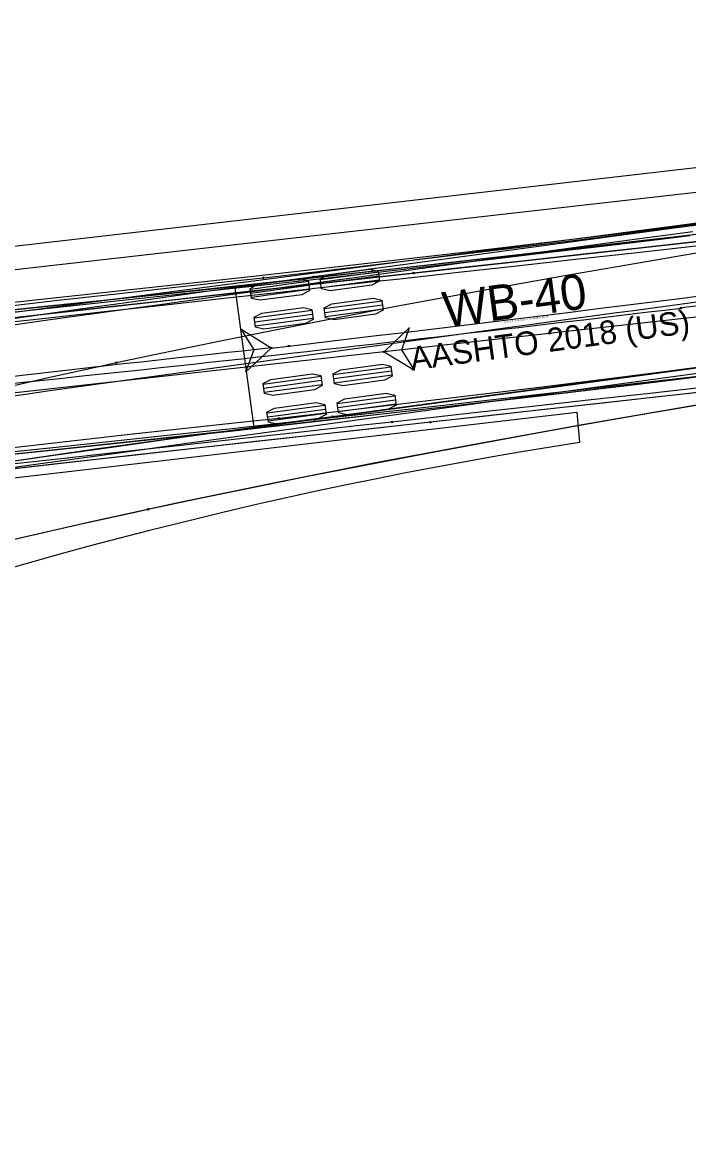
# Model space of a CAD drawing. Extents: x 1600240 to 1604759, y 285789 to 289704.
# Drawn here: x 1601719 to 1601756.7, y 286670.3 to 286733.3 of the extents above; entities that cross this region are included whole.
import ezdxf

# ---------------------------------------------------------------- set-up
doc = ezdxf.new("R2010")
doc.units = 0
for name, color, linetype in [('MT_P_CL_Double_Solid', 7, 'Continuous'), ('MT_P_Drums', 7, 'Continuous'), ('MT_X_CL_Double_Solid', 7, 'Continuous'), ('MT_X_Edge_Line', 7, 'Continuous'), ('PM_X_Edge_Line', 7, 'Continuous'), ('TR_Turning_Path2', 7, 'Continuous'), ('TR_Turning_Path3', 7, 'Continuous'), ('TR_Turning_Path4', 7, 'Continuous')]:
    doc.layers.add(name, color=color, linetype=linetype)

msp = doc.modelspace()

# ---------------------------------------------------------------- linework, layer by layer
at = {"layer": 'MT_P_CL_Double_Solid'}
for p, q in [((1601763.729, 286722.673), (1601731.025, 286718.262)), ((1601739.133, 286719.124), (1601735.862, 286718.683)), ((1601739.163, 286718.897), (1601735.893, 286718.456)), ((1601731.025, 286718.262), (1601732.095, 286710.333)), ((1601735.169, 286718.589), (1601731.898, 286718.148)), ((1601735.199, 286718.362), (1601731.929, 286717.921)), ((1601735.23, 286718.135), (1601731.959, 286717.694)), ((1601739.194, 286718.67), (1601735.924, 286718.229)), ((1601735.389, 286716.954), (1601732.119, 286716.513)), ((1601739.353, 286717.489), (1601736.083, 286717.048)), ((1601739.384, 286717.262), (1601736.113, 286716.82)), ((1601739.414, 286717.035), (1601736.144, 286716.593)), ((1601735.42, 286716.727), (1601732.149, 286716.286)), ((1601735.45, 286716.5), (1601732.18, 286716.059)), ((1601732.095, 286710.333), (1601764.798, 286714.745)), ((1601739.859, 286713.739), (1601736.589, 286713.298)), ((1601735.895, 286713.205), (1601732.624, 286712.764)), ((1601739.89, 286713.512), (1601736.619, 286713.071)), ((1601739.92, 286713.285), (1601736.65, 286712.844)), ((1601735.926, 286712.978), (1601732.655, 286712.536)), ((1601735.956, 286712.75), (1601732.686, 286712.309)), ((1601740.08, 286712.104), (1601736.809, 286711.663)), ((1601740.11, 286711.877), (1601736.84, 286711.436)), ((1601736.115, 286711.569), (1601732.845, 286711.128)), ((1601736.146, 286711.342), (1601732.876, 286710.901)), ((1601740.141, 286711.65), (1601736.87, 286711.209)), ((1601736.177, 286711.115), (1601732.906, 286710.674))]:
    msp.add_line(p, q, dxfattribs=at)
for points in [[(1601732.634, 286718.801), (1601734.278, 286718.988), (1601737.577, 286719.38), (1601740.876, 286719.776), (1601744.174, 286720.176), (1601747.472, 286720.58), (1601750.77, 286720.987), (1601754.067, 286721.398), (1601757.363, 286721.813), (1601760.659, 286722.232), (1601763.955, 286722.654), (1601767.25, 286723.081), (1601770.545, 286723.51), (1601773.18, 286723.857)], [(1601672.219, 286711.984), (1601685.063, 286713.582), (1601700.59, 286715.414), (1601713.62, 286716.886), (1601732.07, 286718.89), (1601743.663, 286720.218), (1601753.593, 286721.41), (1601763.517, 286722.646)], [(1601681.152, 286712.493), (1601684.467, 286712.952), (1601687.783, 286713.404), (1601691.1, 286713.849), (1601694.418, 286714.287), (1601697.737, 286714.717), (1601701.057, 286715.14), (1601704.377, 286715.556), (1601707.698, 286715.965), (1601711.02, 286716.367), (1601714.343, 286716.761), (1601717.667, 286717.148), (1601720.992, 286717.528), (1601724.317, 286717.901), (1601727.644, 286718.267), (1601730.971, 286718.625), (1601732.634, 286718.802)], [(1601694.857, 286712.715), (1601696.509, 286713.015), (1601699.811, 286713.595), (1601703.114, 286714.151), (1601706.418, 286714.686), (1601709.722, 286715.203), (1601713.026, 286715.704), (1601716.33, 286716.193), (1601719.634, 286716.671), (1601722.937, 286717.14), (1601726.24, 286717.601), (1601729.542, 286718.056), (1601732.844, 286718.506), (1601735.485, 286718.863)], [(1601733.079, 286714.826), (1601731.373, 286715.87), (1601732.085, 286714.721), (1601731.629, 286713.449), (1601733.079, 286714.826)], [(1601733.524, 286710.851), (1601735.19, 286711.04), (1601738.499, 286711.433), (1601741.807, 286711.831), (1601745.115, 286712.232), (1601748.422, 286712.636), (1601751.728, 286713.045), (1601755.034, 286713.457), (1601758.34, 286713.873), (1601761.645, 286714.293), (1601764.95, 286714.716), (1601768.254, 286715.144), (1601771.558, 286715.575), (1601774.2, 286715.923)], [(1601766.855, 286714.948), (1601756.613, 286713.641), (1601735.143, 286710.744), (1601723.256, 286709.106), (1601713.613, 286707.703), (1601704.68, 286706.301), (1601700.864, 286705.659), (1601697.061, 286704.985), (1601693.588, 286704.335), (1601690.131, 286703.651), (1601686.696, 286702.929), (1601683.595, 286702.237), (1601680.21, 286701.432)], [(1601733.079, 286714.826), (1601733.411, 286714.861), (1601733.742, 286714.898), (1601734.073, 286714.936)], [(1601679.001, 286704.144), (1601682.315, 286704.578), (1601685.611, 286705.035), (1601688.909, 286705.484), (1601692.208, 286705.926), (1601695.508, 286706.361), (1601698.809, 286706.789), (1601702.111, 286707.21), (1601705.414, 286707.624), (1601708.718, 286708.03), (1601712.023, 286708.43), (1601715.328, 286708.822), (1601718.635, 286709.207), (1601721.942, 286709.585), (1601725.25, 286709.956), (1601728.559, 286710.319), (1601731.869, 286710.676), (1601733.524, 286710.851)], [(1601696.31, 286704.848), (1601697.928, 286705.142), (1601701.168, 286705.711), (1601704.418, 286706.258), (1601707.676, 286706.785), (1601710.942, 286707.296), (1601714.213, 286707.793), (1601717.489, 286708.277), (1601720.769, 286708.752), (1601724.053, 286709.218), (1601727.339, 286709.677), (1601730.629, 286710.13), (1601733.92, 286710.579), (1601736.554, 286710.935)]]:
    msp.add_lwpolyline(points, dxfattribs=at)
for points in [[(1601739.125, 286719.18), (1601739.202, 286718.613), (1601738.767, 286718.381), (1601736.412, 286718.063), (1601735.931, 286718.172), (1601735.855, 286718.739), (1601736.289, 286718.972), (1601738.644, 286719.289)], [(1601735.161, 286718.646), (1601735.237, 286718.079), (1601734.803, 286717.846), (1601732.448, 286717.529), (1601731.967, 286717.638), (1601731.891, 286718.204), (1601732.325, 286718.437), (1601734.68, 286718.755)], [(1601739.346, 286717.545), (1601739.422, 286716.978), (1601738.987, 286716.746), (1601736.633, 286716.428), (1601736.152, 286716.537), (1601736.075, 286717.104), (1601736.51, 286717.336), (1601738.865, 286717.654)], [(1601735.382, 286717.01), (1601735.458, 286716.443), (1601735.023, 286716.211), (1601732.668, 286715.893), (1601732.188, 286716.002), (1601732.111, 286716.569), (1601732.546, 286716.802), (1601734.901, 286717.119)], [(1601733.079, 286714.826), (1601731.373, 286715.87), (1601732.085, 286714.721), (1601731.629, 286713.449)], [(1601739.851, 286713.796), (1601739.928, 286713.229), (1601739.493, 286712.996), (1601737.138, 286712.679), (1601736.657, 286712.788), (1601736.581, 286713.355), (1601737.016, 286713.587), (1601739.37, 286713.905)], [(1601735.887, 286713.261), (1601735.964, 286712.694), (1601735.529, 286712.462), (1601733.174, 286712.144), (1601732.693, 286712.253), (1601732.617, 286712.82), (1601733.052, 286713.052), (1601735.406, 286713.37)], [(1601740.072, 286712.16), (1601740.148, 286711.594), (1601739.714, 286711.361), (1601737.359, 286711.043), (1601736.878, 286711.152), (1601736.802, 286711.719), (1601737.236, 286711.952), (1601739.591, 286712.27)], [(1601736.108, 286711.626), (1601736.184, 286711.059), (1601735.749, 286710.826), (1601733.395, 286710.509), (1601732.914, 286710.618), (1601732.837, 286711.185), (1601733.272, 286711.417), (1601735.627, 286711.735)]]:
    msp.add_lwpolyline(points, close=True, dxfattribs=at)
for centre in [(1601732.634, 286718.802), (1601732.634, 286718.801), (1601735.485, 286718.863), (1601733.079, 286714.826), (1601733.079, 286714.826), (1601734.073, 286714.936), (1601734.073, 286714.936), (1601733.524, 286710.851), (1601733.524, 286710.851), (1601736.554, 286710.935)]:
    msp.add_circle(centre, 0.0417, dxfattribs=at)
for centre, radius, start, end in [((1601391.859, 289612.428), 2917.631, 276.735827, 277.519878), ((1601894.794, 285182.169), 1541.166, 96.023133, 97.98361)]:
    msp.add_arc(centre, radius, start, end, dxfattribs=at)
at = {"layer": 'MT_P_Drums'}
msp.add_lwpolyline([(1601651.674, 286672.718), (1601652.125, 286684.662), (1601652.525, 286688.936), (1601653.402, 286691.708), (1601655.048, 286694.594), (1601656.044, 286695.898), (1601657.427, 286697.431), (1601662.506, 286700.264), (1601665.945, 286701.335), (1601670.628, 286701.946), (1601684.136, 286703.517), (1601693.804, 286704.631), (1601700.317, 286705.382), (1601721.592, 286707.834), (1601750.383, 286711.195), (1601750.521, 286709.478)], dxfattribs=at)
msp.add_arc((1601791.398, 286448.282), 264.375, 98.89462, 121.90447, dxfattribs=at)
at = {"layer": 'MT_X_CL_Double_Solid'}
msp.add_line((1601542.236, 286699.291), (1601771.801, 286725.312), dxfattribs=at)
at = {"layer": 'MT_X_Edge_Line'}
msp.add_arc((1602837.866, 287782.942), 1921, 229.7619, 229.7619, dxfattribs=at)
at = {"layer": 'PM_X_Edge_Line'}
msp.add_lwpolyline([(1601769.774, 286741.911), (1601771.337, 286726.682), (1601631.829, 286710.563)], dxfattribs=at)
at = {"layer": 'TR_Turning_Path2'}
for points in [[(1601669.103, 286712.045), (1601700.18, 286715.116), (1601715.589, 286716.684), (1601730.661, 286718.281), (1601742.046, 286719.533), (1601754.096, 286720.901), (1601773.44, 286723.342), (1601787.142, 286724.982), (1601798.854, 286726.301), (1601810.575, 286727.546)], [(1601794.564, 286725.604), (1601792.905, 286725.416), (1601789.589, 286725.037), (1601786.274, 286724.655), (1601782.96, 286724.269), (1601779.648, 286723.882), (1601776.337, 286723.494), (1601773.027, 286723.105), (1601769.717, 286722.717), (1601766.408, 286722.329), (1601763.099, 286721.943), (1601759.79, 286721.558), (1601756.482, 286721.175), (1601753.174, 286720.794), (1601749.866, 286720.416), (1601746.558, 286720.04), (1601743.25, 286719.668), (1601739.941, 286719.299), (1601736.633, 286718.933), (1601734.647, 286718.715)], [(1601756.765, 286721.185), (1601755.122, 286720.98), (1601751.819, 286720.584), (1601748.514, 286720.194), (1601745.209, 286719.808), (1601741.904, 286719.426), (1601738.598, 286719.049), (1601735.291, 286718.677), (1601731.984, 286718.309), (1601728.676, 286717.945), (1601725.368, 286717.586), (1601722.06, 286717.231), (1601718.751, 286716.881), (1601715.441, 286716.536), (1601712.131, 286716.195), (1601708.821, 286715.858), (1601705.51, 286715.526), (1601702.199, 286715.199), (1601698.887, 286714.876), (1601696.9, 286714.684)], [(1601800.714, 286718.239), (1601789.895, 286717.02), (1601759.407, 286713.451), (1601753.853, 286712.753), (1601747.958, 286712.057), (1601730.919, 286710.125), (1601720.098, 286708.962), (1601709.27, 286707.846), (1601682.57, 286705.249), (1601679.627, 286704.866)], [(1601734.647, 286718.715), (1601733.323, 286718.57), (1601730.012, 286718.211), (1601726.7, 286717.855), (1601723.388, 286717.502), (1601720.075, 286717.153), (1601716.762, 286716.806), (1601713.448, 286716.463), (1601710.134, 286716.122), (1601706.82, 286715.784), (1601703.505, 286715.449), (1601700.19, 286715.117), (1601697.869, 286714.886)], [(1601795.46, 286717.654), (1601793.807, 286717.467), (1601790.501, 286717.09), (1601787.195, 286716.708), (1601783.887, 286716.323), (1601780.579, 286715.937), (1601777.269, 286715.549), (1601773.96, 286715.16), (1601770.649, 286714.771), (1601767.338, 286714.383), (1601764.026, 286713.996), (1601760.713, 286713.611), (1601757.4, 286713.228), (1601754.086, 286712.846), (1601750.772, 286712.467), (1601747.457, 286712.091), (1601744.141, 286711.718), (1601740.825, 286711.348), (1601737.508, 286710.981), (1601735.518, 286710.762)], [(1601757.27, 286717.217), (1601756.939, 286717.173), (1601756.609, 286717.131), (1601756.278, 286717.09)], [(1601757.775, 286713.249), (1601756.11, 286713.041), (1601752.795, 286712.644), (1601749.48, 286712.252), (1601746.164, 286711.865), (1601742.847, 286711.482), (1601739.531, 286711.104), (1601736.213, 286710.73), (1601732.895, 286710.361), (1601729.577, 286709.996), (1601726.258, 286709.636), (1601722.939, 286709.28), (1601719.619, 286708.929), (1601716.298, 286708.582), (1601712.978, 286708.24), (1601709.656, 286707.902), (1601706.335, 286707.569), (1601703.013, 286707.24), (1601699.69, 286706.916), (1601697.696, 286706.724)], [(1601735.518, 286710.762), (1601734.191, 286710.617), (1601730.871, 286710.257), (1601727.551, 286709.901), (1601724.231, 286709.547), (1601720.911, 286709.197), (1601717.591, 286708.849), (1601714.27, 286708.505), (1601710.949, 286708.164), (1601707.628, 286707.825), (1601704.307, 286707.49), (1601700.985, 286707.157), (1601698.66, 286706.925)]]:
    msp.add_lwpolyline(points, dxfattribs=at)
for centre in [(1601734.647, 286718.715), (1601734.647, 286718.715), (1601756.278, 286717.09), (1601756.278, 286717.09), (1601735.518, 286710.762), (1601735.518, 286710.762)]:
    msp.add_circle(centre, 0.0417, dxfattribs=at)
msp.add_arc((1601463.335, 289147.13), 2447.634, 275.485119, 276.873862, dxfattribs=at)
at = {"layer": 'TR_Turning_Path3'}
for points in [[(1601680.686, 286714.097), (1601683.163, 286714.353), (1601685.669, 286714.537), (1601688.205, 286714.645), (1601690.406, 286714.676), (1601692.631, 286714.648), (1601694.129, 286714.596), (1601697.519, 286714.425), (1601699.744, 286714.36), (1601720.817, 286717.161), (1601764.415, 286722.867), (1601784.553, 286725.478), (1601803.318, 286727.87)], [(1601724.306, 286713.999), (1601726.924, 286714.557), (1601730.2, 286715.236), (1601733.48, 286715.897), (1601736.762, 286716.541), (1601740.046, 286717.169), (1601743.333, 286717.783), (1601746.622, 286718.382), (1601749.912, 286718.968), (1601753.204, 286719.543), (1601756.497, 286720.106), (1601759.792, 286720.658), (1601763.088, 286721.201), (1601766.384, 286721.734), (1601769.682, 286722.258), (1601772.98, 286722.775), (1601776.279, 286723.283), (1601779.579, 286723.785), (1601782.879, 286724.28), (1601786.18, 286724.768), (1601789.482, 286725.25), (1601792.784, 286725.726), (1601793.114, 286725.774)], [(1601837.307, 286723.523), (1601789.719, 286716.695), (1601780.282, 286715.295), (1601771.186, 286713.891), (1601764.052, 286712.745), (1601757.255, 286711.613), (1601750.796, 286710.493), (1601744.675, 286709.387), (1601738.892, 286708.296), (1601733.128, 286707.158), (1601727.706, 286706.034), (1601722.631, 286704.93), (1601717.28, 286703.702), (1601712.293, 286702.491), (1601707.359, 286701.22), (1601702.782, 286699.968), (1601698.244, 286698.646), (1601694.036, 286697.34), (1601689.85, 286695.952), (1601685.981, 286694.581), (1601682.13, 286693.119), (1601678.597, 286691.681)], [(1601691.597, 286713.649), (1601694.003, 286713.628), (1601697.402, 286713.668), (1601700.755, 286713.823), (1601704.055, 286714.129), (1601707.344, 286714.582), (1601710.65, 286715.047), (1601713.956, 286715.51), (1601717.261, 286715.973), (1601720.567, 286716.434), (1601723.874, 286716.895), (1601727.18, 286717.354), (1601730.486, 286717.812), (1601733.793, 286718.268), (1601737.1, 286718.724), (1601740.407, 286719.178), (1601743.714, 286719.631), (1601747.021, 286720.083), (1601750.329, 286720.534), (1601753.636, 286720.984), (1601756.944, 286721.432)], [(1601726.1, 286705.69), (1601728.677, 286706.239), (1601731.905, 286706.909), (1601735.14, 286707.561), (1601738.38, 286708.197), (1601741.625, 286708.817), (1601744.876, 286709.424), (1601748.131, 286710.017), (1601751.389, 286710.598), (1601754.652, 286711.167), (1601757.917, 286711.725), (1601761.186, 286712.273), (1601764.457, 286712.812), (1601767.731, 286713.341), (1601771.007, 286713.862), (1601774.286, 286714.376), (1601777.566, 286714.881), (1601780.848, 286715.38), (1601784.132, 286715.872), (1601787.417, 286716.358), (1601790.703, 286716.838), (1601793.991, 286717.313), (1601794.32, 286717.36)], [(1601678.663, 286700.888), (1601681.768, 286702.084), (1601684.9, 286703.227), (1601688.056, 286704.32), (1601691.232, 286705.366), (1601694.425, 286706.369), (1601697.634, 286707.331), (1601700.855, 286708.255), (1601704.088, 286709.144), (1601707.331, 286710), (1601710.582, 286710.824), (1601713.84, 286711.621), (1601717.105, 286712.39), (1601720.375, 286713.135), (1601723.65, 286713.857), (1601724.306, 286713.999)], [(1601692.966, 286705.812), (1601695.231, 286705.755), (1601698.505, 286705.76), (1601701.815, 286705.899), (1601705.155, 286706.206), (1601708.475, 286706.662), (1601711.778, 286707.127), (1601715.08, 286707.59), (1601718.383, 286708.052), (1601721.686, 286708.513), (1601724.989, 286708.973), (1601728.292, 286709.431), (1601731.596, 286709.889), (1601734.9, 286710.345), (1601738.204, 286710.8), (1601741.508, 286711.254), (1601744.812, 286711.707), (1601748.116, 286712.158), (1601751.421, 286712.609), (1601754.725, 286713.058), (1601758.03, 286713.506)], [(1601678.882, 286691.8), (1601681.799, 286692.988), (1601684.757, 286694.127), (1601687.753, 286695.22), (1601690.782, 286696.269), (1601693.84, 286697.276), (1601696.923, 286698.245), (1601700.03, 286699.176), (1601703.157, 286700.073), (1601706.302, 286700.937), (1601709.463, 286701.771), (1601712.638, 286702.577), (1601715.827, 286703.356), (1601719.026, 286704.11), (1601722.236, 286704.841), (1601725.455, 286705.551), (1601726.1, 286705.69)]]:
    msp.add_lwpolyline(points, dxfattribs=at)
for centre in [(1601724.306, 286713.999), (1601724.306, 286713.999), (1601726.1, 286705.69), (1601726.1, 286705.69)]:
    msp.add_circle(centre, 0.0417, dxfattribs=at)
msp.add_arc((1603014.058, 277436.321), 9365.825, 97.5429943, 98.0308259, dxfattribs=at)
at = {"layer": 'TR_Turning_Path4'}
for p, q in [((1601797.19, 286721.026), (1601739.469, 286714.61)), ((1601797.19, 286721.026), (1601739.469, 286714.61)), ((1601739.469, 286714.61), (1601681.477, 286708.164)), ((1601739.469, 286714.61), (1601681.477, 286708.164))]:
    msp.add_line(p, q, dxfattribs=at)
for points in [[(1601669.592, 286710.978), (1601682.484, 286712.511), (1601695.75, 286714.026), (1601859.938, 286732.277)], [(1601799.13, 286725.518), (1601797.141, 286725.297), (1601793.827, 286724.928), (1601790.514, 286724.56), (1601787.2, 286724.192), (1601783.886, 286723.823), (1601780.572, 286723.455), (1601777.258, 286723.087), (1601773.944, 286722.718), (1601770.631, 286722.35), (1601767.317, 286721.982), (1601764.003, 286721.613), (1601760.689, 286721.245), (1601757.375, 286720.876), (1601754.061, 286720.508), (1601750.748, 286720.14), (1601747.434, 286719.771), (1601744.12, 286719.403), (1601741.137, 286719.072)], [(1601796.748, 286725.002), (1601793.43, 286724.633), (1601790.113, 286724.264), (1601786.796, 286723.895), (1601783.479, 286723.527), (1601780.161, 286723.158), (1601776.844, 286722.789), (1601773.527, 286722.42), (1601770.21, 286722.052), (1601766.892, 286721.683), (1601763.575, 286721.314), (1601760.258, 286720.945), (1601756.941, 286720.577), (1601753.623, 286720.208), (1601750.306, 286719.839), (1601746.989, 286719.47), (1601743.672, 286719.102), (1601740.354, 286718.733), (1601739.028, 286718.585)], [(1601860.943, 286723.837), (1601725.648, 286708.792), (1601707.965, 286706.783), (1601703.38, 286706.233), (1601699.455, 286705.729), (1601694.572, 286705.026), (1601690.373, 286704.315), (1601686.858, 286703.609), (1601684.96, 286703.174), (1601683.392, 286702.782), (1601681.527, 286702.272), (1601679.989, 286701.812)], [(1601741.137, 286719.072), (1601740.806, 286719.035), (1601737.503, 286718.667), (1601734.2, 286718.3), (1601730.897, 286717.932), (1601727.594, 286717.563), (1601724.29, 286717.193), (1601720.987, 286716.822), (1601717.683, 286716.449), (1601715.04, 286716.15)], [(1601739.028, 286718.585), (1601737.039, 286718.364), (1601733.725, 286717.996), (1601730.412, 286717.628), (1601727.098, 286717.259), (1601723.784, 286716.891), (1601720.47, 286716.523), (1601717.156, 286716.154), (1601713.842, 286715.786), (1601710.529, 286715.418), (1601707.215, 286715.049), (1601703.901, 286714.681), (1601700.587, 286714.312), (1601697.273, 286713.944), (1601693.959, 286713.576), (1601690.646, 286713.207), (1601687.332, 286712.839), (1601684.018, 286712.471), (1601681.035, 286712.139)], [(1601797.632, 286717.05), (1601794.314, 286716.682), (1601790.997, 286716.313), (1601787.68, 286715.944), (1601784.363, 286715.576), (1601781.045, 286715.207), (1601777.728, 286714.838), (1601774.411, 286714.469), (1601771.094, 286714.101), (1601767.776, 286713.732), (1601764.459, 286713.363), (1601761.142, 286712.994), (1601757.825, 286712.626), (1601754.507, 286712.257), (1601751.19, 286711.888), (1601747.873, 286711.519), (1601744.556, 286711.151), (1601741.238, 286710.782), (1601739.911, 286710.634)], [(1601800.069, 286717.07), (1601798.08, 286716.849), (1601794.767, 286716.48), (1601791.453, 286716.112), (1601788.139, 286715.744), (1601784.825, 286715.375), (1601781.511, 286715.007), (1601778.197, 286714.639), (1601774.884, 286714.27), (1601771.57, 286713.902), (1601768.256, 286713.534), (1601764.942, 286713.165), (1601761.628, 286712.797), (1601758.314, 286712.429), (1601755.001, 286712.06), (1601751.687, 286711.692), (1601748.373, 286711.323), (1601745.059, 286710.955), (1601742.077, 286710.624)], [(1601739.469, 286714.61), (1601741.181, 286713.575), (1601740.463, 286714.72), (1601740.912, 286715.995), (1601739.469, 286714.61)], [(1601739.469, 286714.61), (1601741.181, 286713.575), (1601740.463, 286714.72), (1601740.912, 286715.995), (1601739.469, 286714.61)], [(1601739.911, 286710.634), (1601737.923, 286710.413), (1601734.609, 286710.045), (1601731.295, 286709.677), (1601727.982, 286709.308), (1601724.668, 286708.94), (1601721.354, 286708.572), (1601718.04, 286708.203), (1601714.726, 286707.835), (1601711.412, 286707.466), (1601708.099, 286707.098), (1601704.785, 286706.73), (1601701.471, 286706.361), (1601698.157, 286705.993), (1601694.843, 286705.625), (1601691.529, 286705.256), (1601688.216, 286704.888), (1601684.902, 286704.52), (1601681.919, 286704.188)], [(1601742.077, 286710.624), (1601741.745, 286710.587), (1601738.442, 286710.219), (1601735.14, 286709.852), (1601731.839, 286709.484), (1601728.538, 286709.116), (1601725.238, 286708.746), (1601721.937, 286708.375), (1601718.638, 286708.003), (1601715.998, 286707.704)]]:
    msp.add_lwpolyline(points, dxfattribs=at)
msp.add_lwpolyline([(1601739.469, 286714.61), (1601741.181, 286713.575), (1601740.463, 286714.72), (1601740.912, 286715.995)], close=True, dxfattribs=at)
msp.add_lwpolyline([(1601739.469, 286714.61), (1601741.181, 286713.575), (1601740.463, 286714.72), (1601740.912, 286715.995)], close=True, dxfattribs=at)
for centre in [(1601741.137, 286719.072), (1601741.137, 286719.072), (1601739.028, 286718.585), (1601739.028, 286718.585), (1601739.469, 286714.61), (1601739.469, 286714.61), (1601739.469, 286714.61), (1601739.469, 286714.61), (1601739.911, 286710.634), (1601739.911, 286710.634), (1601742.077, 286710.624), (1601742.077, 286710.624)]:
    msp.add_circle(centre, 0.0417, dxfattribs=at)

# ---------------------------------------------------------------- texts
at = {"layer": 'MT_P_CL_Double_Solid'}
for s, height, p in [('WB-40', 2, (1601742.935, 286715.993)), ('AASHTO 2018 (US)', 1.33333, (1601741.031, 286713.55)), ('(c) 2024 Transoft Solutions, Inc. All rights reserved.', 0.08, (1601746.294, 286716.245))]:
    msp.add_text(s, height=height, rotation=7.68228, dxfattribs=at).set_placement(p)

doc.saveas('drawing.dxf')
